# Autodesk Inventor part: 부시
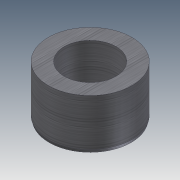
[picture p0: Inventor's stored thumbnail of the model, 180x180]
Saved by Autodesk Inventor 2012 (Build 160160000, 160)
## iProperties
Company: 한국ATC센터
Created: 2014-11
Part Number: 부시
Document SubType Name: Modeling
Designer: KYOUNG IL JANG
Density: 7.86 g/cm^3
Material: 강, 연강
Mass: 167.601 g
Surface Area: 70.0223 cm^2
Volume: 21.3233 cm^3
Author: KYOUNG IL JANG
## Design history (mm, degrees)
sketch "스케치1"
  geometry: C1 r 21 at (0, 0); C2 r 13 at (0, 0); 1 further point
  constraints: 2 centre point, 2 coincident
  dimensions: "d4" = 26 diameter of C2; "d5" = 42 diameter of C1
extrude "돌출1" new body sketch "스케치1" distance "d0" = 25; taper "d1" = 0 deg
chamfer "모따기1" distance "d6" = 1.5; stored, may be unused: second distance "d7" = 2, angle "d8" = 15 deg
node "솔리드1"
